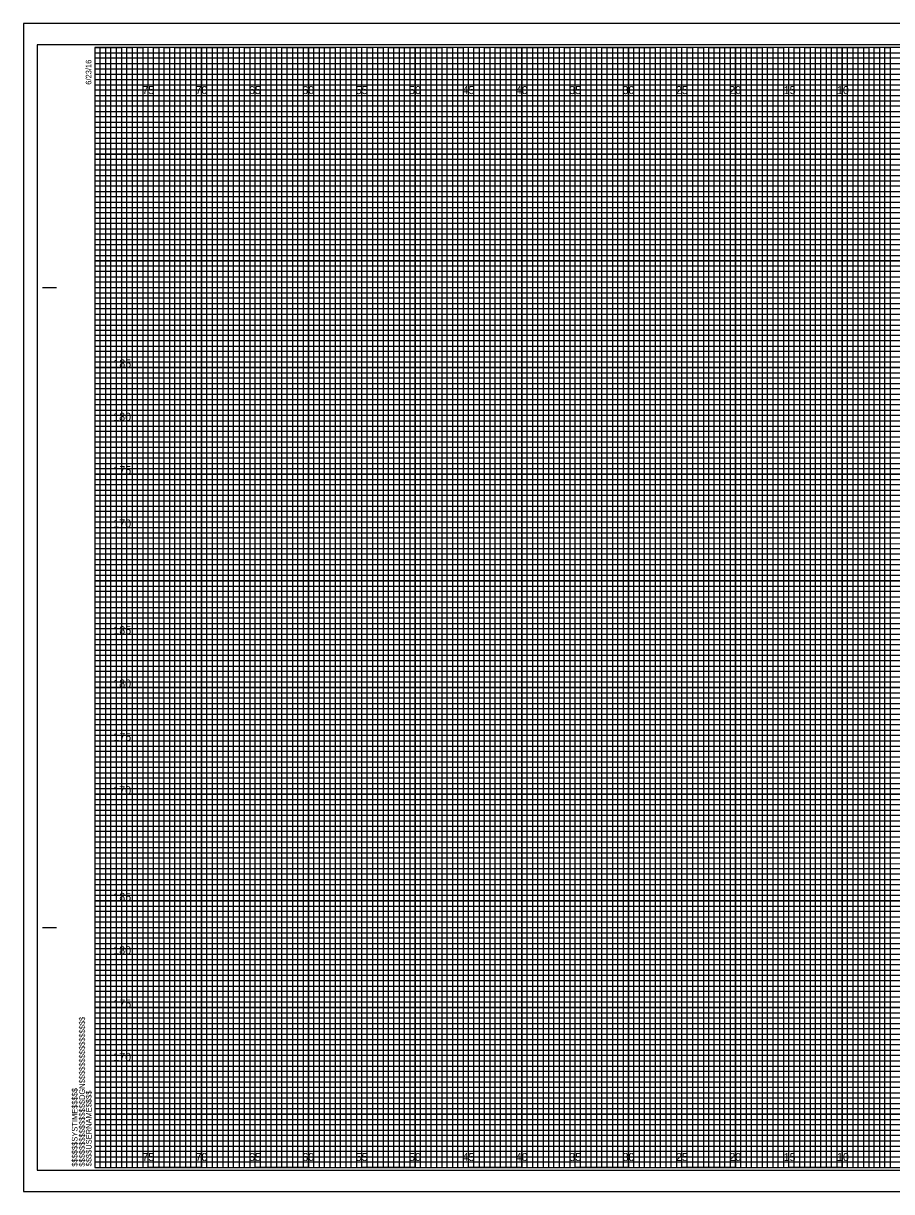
# Model space of a CAD drawing. Extents: x -7 to 162, y -2 to 107.
# Drawn here: x -6.7 to 74.6, y -2.3 to 107.3 of the extents above; entities that cross this region are included whole.
import ezdxf

# ---------------------------------------------------------------- set-up
doc = ezdxf.new("R2010")
doc.units = 0
for name, color, linetype in [('Prop XS Elevation Labels', 7, 'Continuous'), ('Prop XS Offset Labels', 7, 'Continuous'), ('Sheet Cross Section CELL', 7, 'Continuous'), ('Sheet Cross Section Grid Major CELL', 7, 'Continuous'), ('Sheet Cross Section Grid Middle CELL', 7, 'Continuous'), ('Sheet Cross Section Grid Minor 1 CELL', 7, 'Continuous'), ('Sheet Cross Section Grid Minor 2 CELL', 7, 'Continuous'), ('Sheet Cutting Line CELL', 7, 'Continuous'), ('Sheet DOT Grid CELL', 7, 'Continuous'), ('Sheet Plot Border Inside CELL', 7, 'Continuous'), ('Sheet Plot Border Outside CELL', 7, 'Continuous')]:
    doc.layers.add(name, color=color, linetype=linetype)

msp = doc.modelspace()

# ---------------------------------------------------------------- linework, layer by layer
at = {"layer": 'Sheet Cross Section CELL'}
for p, q in [((-4.9, 82.5), (-3.65, 82.5)), ((-4.85, 82.5), (-3.6, 82.5)), ((-4.9, 22.5), (-3.65, 22.5)), ((-4.85, 22.5), (-3.6, 22.5)), ((0, 0), (0, 0)), ((0, 0), (0, 0)), ((0, 0), (0, 0)), ((0, 0), (0, 0)), ((0, 0), (0, 0)), ((0, 0), (0, 0)), ((0, 0), (0, 0))]:
    msp.add_line(p, q, dxfattribs=at)
msp.add_lwpolyline([(160, 105), (0, 105), (0, 0), (160, 0)], close=True, dxfattribs=at)
at = {"layer": 'Sheet Cross Section Grid Major CELL'}
for p, q in [((5, 105), (0, 105)), ((5, 0), (5, 105)), ((15, 105), (10, 105)), ((10, 105), (10, 0)), ((15, 0), (15, 105)), ((25, 105), (20, 105)), ((20, 105), (20, 0)), ((25, 0), (25, 105)), ((35, 105), (30, 105)), ((30, 105), (30, 0)), ((35, 0), (35, 105)), ((45, 105), (40, 105)), ((40, 105), (40, 0)), ((45, 0), (45, 105)), ((55, 105), (50, 105)), ((50, 105), (50, 0)), ((55, 0), (55, 105)), ((65, 105), (60, 105)), ((60, 105), (60, 0)), ((65, 0), (65, 105)), ((75, 105), (70, 105)), ((70, 105), (70, 0)), ((10, 0), (5, 0)), ((20, 0), (15, 0)), ((30, 0), (25, 0)), ((40, 0), (35, 0)), ((50, 0), (45, 0)), ((60, 0), (55, 0)), ((70, 0), (65, 0))]:
    msp.add_line(p, q, dxfattribs=at)
for points in [[(0, 100), (160, 100), (160, 95), (0, 95)], [(0, 90), (160, 90), (160, 85), (0, 85)], [(0, 80), (160, 80), (160, 75), (0, 75)], [(0, 70), (160, 70), (160, 65), (0, 65)], [(0, 60), (160, 60), (160, 55), (0, 55)], [(0, 50), (160, 50), (160, 45), (0, 45)], [(0, 40), (160, 40), (160, 35), (0, 35)], [(0, 30), (160, 30), (160, 25), (0, 25)], [(0, 20), (160, 20), (160, 15), (0, 15)], [(0, 10), (160, 10), (160, 5), (0, 5)]]:
    msp.add_lwpolyline(points, dxfattribs=at)
at = {"layer": 'Sheet Cross Section Grid Middle CELL'}
for points in [[(0, 105), (2.5, 105), (2.5, 0), (7.5, 0), (7.5, 105), (12.5, 105), (12.5, 0), (17.5, 0), (17.5, 105), (22.5, 105), (22.5, 0), (27.5, 0), (27.5, 105), (32.5, 105), (32.5, 0), (37.5, 0), (37.5, 105), (42.5, 105), (42.5, 0), (47.5, 0), (47.5, 105), (52.5, 105), (52.5, 0), (57.5, 0), (57.5, 105), (62.5, 105), (62.5, 0), (67.5, 0), (67.5, 105), (72.5, 105), (72.5, 0), (77.5, 0)], [(0, 102.5), (137.5, 102.5)], [(0, 92.5), (160, 92.5), (160, 97.5), (0, 97.5)], [(0, 82.5), (160, 82.5), (160, 87.5), (0, 87.5)], [(0, 72.5), (160, 72.5), (160, 77.5), (0, 77.5)], [(0, 62.5), (160, 62.5), (160, 67.5), (0, 67.5)], [(0, 52.5), (160, 52.5), (160, 57.5), (0, 57.5)], [(0, 42.5), (160, 42.5), (160, 47.5), (0, 47.5)], [(0, 32.5), (160, 32.5), (160, 37.5), (0, 37.5)], [(0, 22.5), (160, 22.5), (160, 27.5), (0, 27.5)], [(0, 12.5), (160, 12.5), (160, 17.5), (0, 17.5)], [(0, 2.5), (160, 2.5), (160, 7.5), (0, 7.5)]]:
    msp.add_lwpolyline(points, dxfattribs=at)
at = {"layer": 'Sheet Cross Section Grid Minor 1 CELL'}
for p, q in [((0, 104.5), (130, 104.5)), ((130, 103.99), (0, 103.99)), ((0, 103.99), (0, 103.5)), ((0, 103.5), (130, 103.5)), ((130, 102.95), (0, 102.95)), ((0, 102.95), (0, 102)), ((0, 102), (160, 102))]:
    msp.add_line(p, q, dxfattribs=at)
for points in [[(0, 101.5), (135, 101.5), (160, 101.5), (160, 101), (0, 101)], [(0, 100.5), (160, 100.5), (160, 99.5), (0, 99.5)], [(0, 99), (160, 99), (160, 98.5), (0, 98.49)], [(0, 98), (160, 98), (160, 97), (0, 97)], [(0, 96.5), (160, 96.5), (160, 96), (0, 96)], [(0, 95.5), (160, 95.5), (160, 94.5), (0, 94.5)], [(0, 94), (160, 94), (160, 93.5), (0, 93.5)], [(0, 93), (160, 93), (160, 92), (0, 92)], [(0, 91.5), (160, 91.5), (160, 91), (0, 91)], [(0, 90.5), (160, 90.5), (160, 89.5), (0, 89.5)], [(0, 89), (160, 89), (160, 88.5), (0, 88.5)], [(0, 88), (160, 88), (160, 86.98), (160, 86.5), (160, 86), (0, 86)], [(0, 87), (160, 87), (160, 86.5), (0, 86.5)], [(0, 85.5), (160, 85.5), (160, 84.5), (0, 84.52)], [(0, 84.52), (160, 84.5), (160, 84), (0, 84)], [(0, 83.5), (160, 83.5), (160, 83), (0, 83)], [(0, 82), (160, 82), (160, 81.5), (0, 81.5)], [(0, 81), (160, 81), (160, 80.5), (0, 80.5)], [(-0.04, 79.45), (160, 79.45), (160, 78.94), (-0.04, 78.94)], [(0, 78.5), (160, 78.5), (160, 78), (0, 78)], [(0, 77), (160, 77), (160, 76.5), (0, 76.5)], [(0, 76), (160, 76), (160, 75.5), (0, 75.5)], [(0, 74.5), (160, 74.5), (160, 74), (0, 74)], [(0, 73.5), (160, 73.5), (160, 73), (0, 73)], [(0, 72), (160, 72), (160, 71.5), (0, 71.5)], [(0, 71), (160, 71), (160, 70.5), (0, 70.5)], [(0, 69.5), (160, 69.5), (160, 68.99), (0, 69)], [(0, 68.5), (160, 68.5), (160, 68), (0, 68)], [(0, 67), (160, 67), (160, 66.5), (0, 66.5)], [(0, 66), (160, 66), (160, 65.5), (0, 65.5)], [(0, 64.5), (160, 64.5), (160, 64), (0, 64)], [(0, 63.5), (160, 63.5), (160, 63), (0, 63)], [(0, 62), (160, 62), (160, 61.5), (0, 61.5)], [(0, 61), (160, 61), (160, 60.5), (0, 60.5)], [(0, 59.5), (160, 59.5), (160, 59), (0, 59)], [(0, 58.5), (160.03, 58.45), (160, 58), (0, 58)], [(0, 57), (160, 57), (160, 56.5), (0, 56.5)], [(0, 56), (160, 56), (160, 55.5), (0, 55.5)], [(0, 54.5), (160, 54.5), (160, 54), (0, 54)], [(0, 53.5), (160, 53.5), (160, 53), (0, 53)], [(0, 52), (160, 52), (160, 51.5), (0, 51.5)], [(0, 51), (160, 51), (160, 50.5), (0, 50.5)], [(0, 49.5), (160, 49.5), (160, 49), (0, 49)], [(0, 48.5), (160, 48.5), (160, 48), (0, 48)], [(0, 47), (160, 47), (160, 46.5), (0, 46.5)], [(0, 46), (160, 46), (160, 45.5), (0, 45.5)], [(0, 44.5), (160, 44.5), (160, 44), (0, 44)], [(0, 43.5), (160, 43.5), (160, 43), (0, 43)], [(0, 42), (160, 42), (160, 41.5), (0, 41.5)], [(0, 41), (160, 41), (160, 40.5), (0, 40.5)], [(0, 39.5), (160, 39.5), (160, 38.99), (0, 39)], [(0, 38.5), (160, 38.5), (160, 38), (0, 38)], [(0, 37), (160, 37), (160, 36.5), (0, 36.5)], [(0, 36), (160, 36), (160, 35.5), (0, 35.5)], [(0, 34.5), (160, 34.5), (160, 34), (0, 34)], [(0, 33.5), (160, 33.5), (160, 33), (0, 33)], [(0, 32), (160, 32), (160, 31.5), (0, 31.5)], [(0, 31), (160, 31), (160, 30.5), (0, 30.5)], [(0, 29.5), (160, 29.5), (160, 29), (0, 29)], [(0, 28.5), (160.03, 28.46), (160, 28), (0, 28)], [(0, 27), (160, 27), (160, 26.5), (0, 26.5)], [(0, 26), (160, 26), (160, 25.5), (0, 25.5)], [(0, 24.5), (160, 24.5), (160, 24), (0, 24)], [(0, 23.5), (160, 23.5), (160, 23), (0, 23)], [(0, 22), (160, 22), (160, 21.5), (0, 21.5)], [(0, 21), (160, 21), (160, 20.5), (0, 20.5)], [(0, 19.5), (160, 19.5), (160, 19), (0, 19)], [(0, 18.5), (160, 18.5), (160, 18), (0, 18)], [(0, 17), (160, 17), (160, 16.5), (0, 16.5)], [(0, 16), (160, 16), (160, 15.5), (0, 15.5)], [(0, 14.5), (160, 14.5), (160, 14), (0, 14)], [(0, 13.5), (160, 13.5), (160, 13), (0, 13)], [(0, 12), (160, 12), (160, 11.5), (0, 11.5)], [(0, 11), (160, 11), (160, 10.5), (0, 10.5)], [(0, 9.5), (160, 9.5), (160, 9), (0, 9)], [(0, 8.5), (160, 8.5), (160, 8), (0, 8)], [(0, 7), (160, 7), (160, 6.5), (0, 6.5)], [(0, 6), (160, 6), (160, 5.5), (0, 5.5)], [(0, 4.5), (160, 4.5), (160, 4), (0, 4)], [(0, 3.5), (160, 3.5), (160, 3), (0, 3)], [(0, 2), (160, 2), (160, 1.5), (0, 1.5)], [(0, 1), (160, 1), (160, 0.5), (0, 0.5)]]:
    msp.add_lwpolyline(points, dxfattribs=at)
at = {"layer": 'Sheet Cross Section Grid Minor 2 CELL'}
for points in [[(0, 0), (0.5, 0), (0.5, 105), (1, 105), (1, 0)], [(1, 0), (1.5, 0), (1.5, 105), (2, 105), (2, 0)], [(2.5, 0), (3, 0), (3, 105), (3.5, 105), (3.5, 0)], [(3.5, 0), (4, 0), (4, 105), (4.5, 105), (4.5, 0)], [(5, 0), (5.5, 0), (5.5, 105), (6, 105), (6, 0)], [(6, 0), (6.5, 0), (6.5, 105), (7, 105), (7, 0)], [(7.5, 0), (8, 0), (8, 105), (8.5, 105), (8.5, 0)], [(8.5, 0), (9, 0), (9, 105), (9.5, 105), (9.5, 0)], [(10, 0), (10.5, 0), (10.5, 105), (11, 105), (11, 0)], [(11, 0), (11.5, 0), (11.5, 105), (12, 105), (12, 0)], [(12.5, 0), (13, 0), (13, 105), (13.5, 105), (13.5, 0)], [(13.5, 0), (14, 0), (14, 105), (14.5, 105), (14.5, 0)], [(15, 0), (15.5, 0), (15.5, 105), (16, 105), (16, 0)], [(16, 0), (16.5, 0), (16.5, 105), (17, 105), (17, 0)], [(17.5, 0), (18, 0), (18, 105), (18.5, 105), (18.5, 0)], [(18.5, 0), (19, 0), (19, 105), (19.5, 105), (19.5, 0)], [(20, 0), (20.5, 0), (20.5, 105), (21, 105), (21, 0)], [(21, 0), (21.5, 0), (21.5, 105), (22, 105), (22, 0)], [(22.5, 0), (23, 0), (23, 105), (23.5, 105), (23.5, 0)], [(23.5, 0), (24, 0), (24, 105), (24.5, 105), (24.5, 0)], [(25, 0), (25.5, 0), (25.5, 105), (26, 105), (26, 0)], [(26, 0), (26.5, 0), (26.5, 105), (27, 105), (27, 0)], [(27.5, 0), (28, 0), (28, 105), (28.5, 105), (28.5, 0)], [(28.5, 0), (29, 0), (29, 105), (29.5, 105), (29.5, 0)], [(30, 0), (30.5, 0), (30.5, 105), (31, 105), (31, 0)], [(31, 0), (31.5, 0), (31.5, 105), (32, 105), (32, 0)], [(32.5, 0), (33, 0), (33, 105), (33.5, 105), (33.5, 0)], [(33.5, 0), (34, 0), (34, 105), (34.5, 105), (34.5, 0)], [(35, 0), (35.5, 0), (35.5, 105), (36, 105), (36, 0)], [(36, 0), (36.5, 0), (36.5, 105), (37, 105), (37, 0)], [(37.5, 0), (38, 0), (38, 105), (38.5, 105), (38.5, 0)], [(38.5, 0), (39, 0), (39, 105), (39.5, 105), (39.5, 0)], [(40, 0), (40.5, 0), (40.5, 105), (41, 105), (41, 0)], [(41, 0), (41.5, 0), (41.5, 105), (42, 105), (42, 0)], [(42.5, 0), (43, 0), (43, 105), (43.5, 105), (43.5, 0)], [(43.5, 0), (44, 0), (44, 105), (44.5, 105), (44.5, 0)], [(45, 0), (45.5, 0), (45.5, 105), (46, 105), (46, 0)], [(46, 0), (46.5, 0), (46.5, 105), (47, 105), (47, 0)], [(47.5, 0), (48, 0), (48, 105), (48.5, 105), (48.5, 0)], [(48.5, 0), (49, 0), (49, 105), (49.5, 105), (49.5, 0)], [(50, 0), (50.5, 0), (50.5, 105), (51, 105), (51, 0)], [(51, 0), (51.5, 0), (51.5, 105), (52, 105), (52, 0)], [(52.5, 0), (53, 0), (53, 105), (53.5, 105), (53.5, 0)], [(53.5, 0), (54, 0), (54, 105), (54.5, 105), (54.5, 0)], [(55, 0), (55.5, 0), (55.5, 105), (56, 105), (56, 0)], [(56, 0), (56.5, 0), (56.5, 105), (57, 105), (57, 0)], [(57.5, 0), (58, 0), (58, 105), (58.5, 105), (58.5, 0)], [(58.5, 0), (59, 0), (59, 105), (59.5, 105), (59.5, 0)], [(60, 0), (60.5, 0), (60.5, 105), (61, 105), (61, 0)], [(61, 0), (61.5, 0), (61.5, 105), (62, 105), (62, 0)], [(62.5, 0), (63, 0), (63, 105), (63.5, 105), (63.5, 0)], [(63.5, 0), (64, 0), (64, 105), (64.5, 105), (64.5, 0)], [(65, 0), (65.5, 0), (65.5, 105), (66, 105), (66, 0)], [(66, 0), (66.5, 0), (66.5, 105), (67, 105), (67, 0)], [(67.5, 0), (68, 0), (68, 105), (68.5, 105), (68.5, 0)], [(68.5, 0), (69, 0), (69, 105), (69.5, 105), (69.5, 0)], [(70, 0), (70.5, 0), (70.5, 105), (71, 105), (71, 0)], [(71, 0), (71.5, 0), (71.5, 105), (72, 105), (72, 0)], [(72.5, 0), (73, 0), (73, 105), (73.5, 105), (73.5, 0)], [(73.5, 0), (74, 0), (74, 105), (74.5, 105), (74.5, 0)]]:
    msp.add_lwpolyline(points, dxfattribs=at)
at = {"layer": 'Sheet Cutting Line CELL'}
for p, q in [((161.65, 107.25), (-6.7, 107.25)), ((-6.7, 107.25), (-6.7, -2.25)), ((-6.7, -2.25), (161.65, -2.25))]:
    msp.add_line(p, q, dxfattribs=at)
at = {"layer": 'Sheet DOT Grid CELL'}
for p, q in [((5, 0), (5, 105)), ((10, 0), (10, 105)), ((15, 0), (15, 105)), ((20, 0), (20, 105)), ((25, 0), (25, 105)), ((30, 0), (30, 105)), ((35, 0), (35, 105)), ((40, 0), (40, 105)), ((45, 0), (45, 105)), ((50, 0), (50, 105)), ((55, 0), (55, 105)), ((60, 0), (60, 105)), ((65, 0), (65, 105)), ((70, 0), (70, 105)), ((0, 100), (160, 100)), ((0, 95), (160, 95)), ((0, 90), (160, 90)), ((0, 85), (160, 85)), ((0, 80), (160, 80)), ((0, 75), (160, 75)), ((0, 70), (160, 70)), ((0, 65), (160, 65)), ((0, 60), (160, 60)), ((0, 55), (160, 55)), ((0, 50), (160, 50)), ((0, 45), (160, 45)), ((0, 40), (160, 40)), ((0, 35), (160, 35)), ((0, 30), (160, 30)), ((0, 25), (160, 25)), ((0, 20), (160, 20)), ((0, 15), (160, 15)), ((0, 10), (160, 10)), ((0, 5), (160, 5))]:
    msp.add_line(p, q, dxfattribs=at)
at = {"layer": 'Sheet Plot Border Inside CELL'}
msp.add_lwpolyline([(-5.4, -0.25), (161.2, -0.25), (161.2, 105.25), (-5.4, 105.25)], close=True, dxfattribs=at)
at = {"layer": 'Sheet Plot Border Outside CELL'}
msp.add_lwpolyline([(-6.7, -2.25), (161.65, -2.25), (161.65, 107.25), (-6.7, 107.25)], close=True, dxfattribs=at)

# ---------------------------------------------------------------- texts
at = {"layer": 'Prop XS Elevation Labels'}
for s, p in [('185', (1.73, 75)), ('180', (1.72, 70)), ('175', (1.73, 65)), ('170', (1.72, 60)), ('185', (1.73, 50)), ('180', (1.72, 45)), ('175', (1.73, 40)), ('170', (1.72, 35)), ('185', (1.73, 25)), ('180', (1.72, 20)), ('175', (1.73, 15)), ('170', (1.72, 10))]:
    msp.add_text(s, height=0.75, dxfattribs=at).set_placement(p)
at = {"layer": 'Prop XS Offset Labels'}
for s, p in [('75', (4.44, 100.62)), ('70', (9.43, 100.62)), ('65', (14.44, 100.62)), ('60', (19.43, 100.62)), ('55', (24.44, 100.62)), ('50', (29.43, 100.62)), ('45', (34.44, 100.62)), ('40', (39.43, 100.62)), ('35', (44.44, 100.62)), ('30', (49.43, 100.62)), ('25', (54.44, 100.62)), ('20', (59.43, 100.62)), ('15', (64.53, 100.62)), ('10', (69.52, 100.62)), ('75', (4.44, 0.62)), ('70', (9.43, 0.62)), ('65', (14.44, 0.62)), ('60', (19.43, 0.62)), ('55', (24.44, 0.62)), ('50', (29.43, 0.62)), ('45', (34.44, 0.62)), ('40', (39.43, 0.62)), ('35', (44.44, 0.62)), ('30', (49.43, 0.62)), ('25', (54.44, 0.62)), ('20', (59.43, 0.62)), ('15', (64.53, 0.62)), ('10', (69.52, 0.62))]:
    msp.add_text(s, height=0.75, dxfattribs=at).set_placement(p)
at = {"layer": 'Sheet Cross Section CELL'}
for s, p in [('6/23/16', (-0.33, 101.5)), ('$$$$$$$$$$$$$$$$DGN$$$$$$$$$$$$$$$$', (-0.94, 0.09)), ('$$$$$$SYSTIME$$$$$', (-1.63, 0.09)), ('$$$$USERNAME$$$$', (-0.31, 0.12))]:
    msp.add_text(s, height=0.525, rotation=90, dxfattribs=at).set_placement(p)

doc.saveas('drawing.dxf')
